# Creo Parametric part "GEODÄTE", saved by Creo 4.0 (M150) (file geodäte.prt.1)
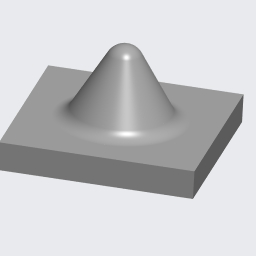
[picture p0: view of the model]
Units: millimeter Kilogram Sec (mmKs); MM, KILOGRAM, SECS
Materials in the file: S235JRG2

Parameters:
  PTC_MATERIAL_NAME = "S235JRG2"
  BENENNUNG = "XXX"
  DATUM = "XX.XX.XX"
  ERSTELLER = "ARINDA"
  TEILETYP = "Fertigungsteil"
  SELECT_EN_NAME = "S235JRG2"
  SELECT_DIN_NAME = "RSt37-2"
  SELECT_DIN_NUMBER = "1.0038"
  SELECT_ASTM_NAME = "A 283 M Grade 2"
  MATERIAL_GROUP = "ME_ST_Baustahl"
  STANDARD_EN_DELIVERYSPEC = "DIN EN 10025"
  STANDARD_DIN_DELIVERYSPEC = "DIN 17100"

Other parameters: MASSE

Created from: ARINDA-STARTTEIL.PRT

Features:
  1. coordinate system "CS0"
  2. datum plane "DTM1", "T_RECHTS_Y-Z"
  3. datum plane "DTM2", "T_OBEN_X-Z"
  4. datum plane "DTM3", "T_VORNE_X-Y"
  5. datum axis "T_X-ACHSE"
  6. datum axis "A_1"
  7. datum axis "A_2"
  8. extrusion "Extrude 1"
  9. revolve "Revolve 1"
  10. datum point "Datum Point id 125", "DATUM_POINT_ID_125"

Other named items: T_BASIC, GRUNDPLATTE, KEGEL, PUNKT, T_Y-ACHSE, T_Z-ACHSE

Layers: 00_STD-ACHSEN, 00_STD-EBENEN, 00_STD-KOORDSYS, 01_PUNKTE, VOLUMENGEOMETRIE

Surfaces: 6 plane, 4 torus, 2 cone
